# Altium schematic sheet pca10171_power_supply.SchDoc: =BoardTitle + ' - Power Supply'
size A3; Organization: Nordic Semiconductor; DocumentNumber: 8; SheetNumber: 8; SheetTotal: 10; CompanyName: Nordic Semiconductor; DocumentSize: A3
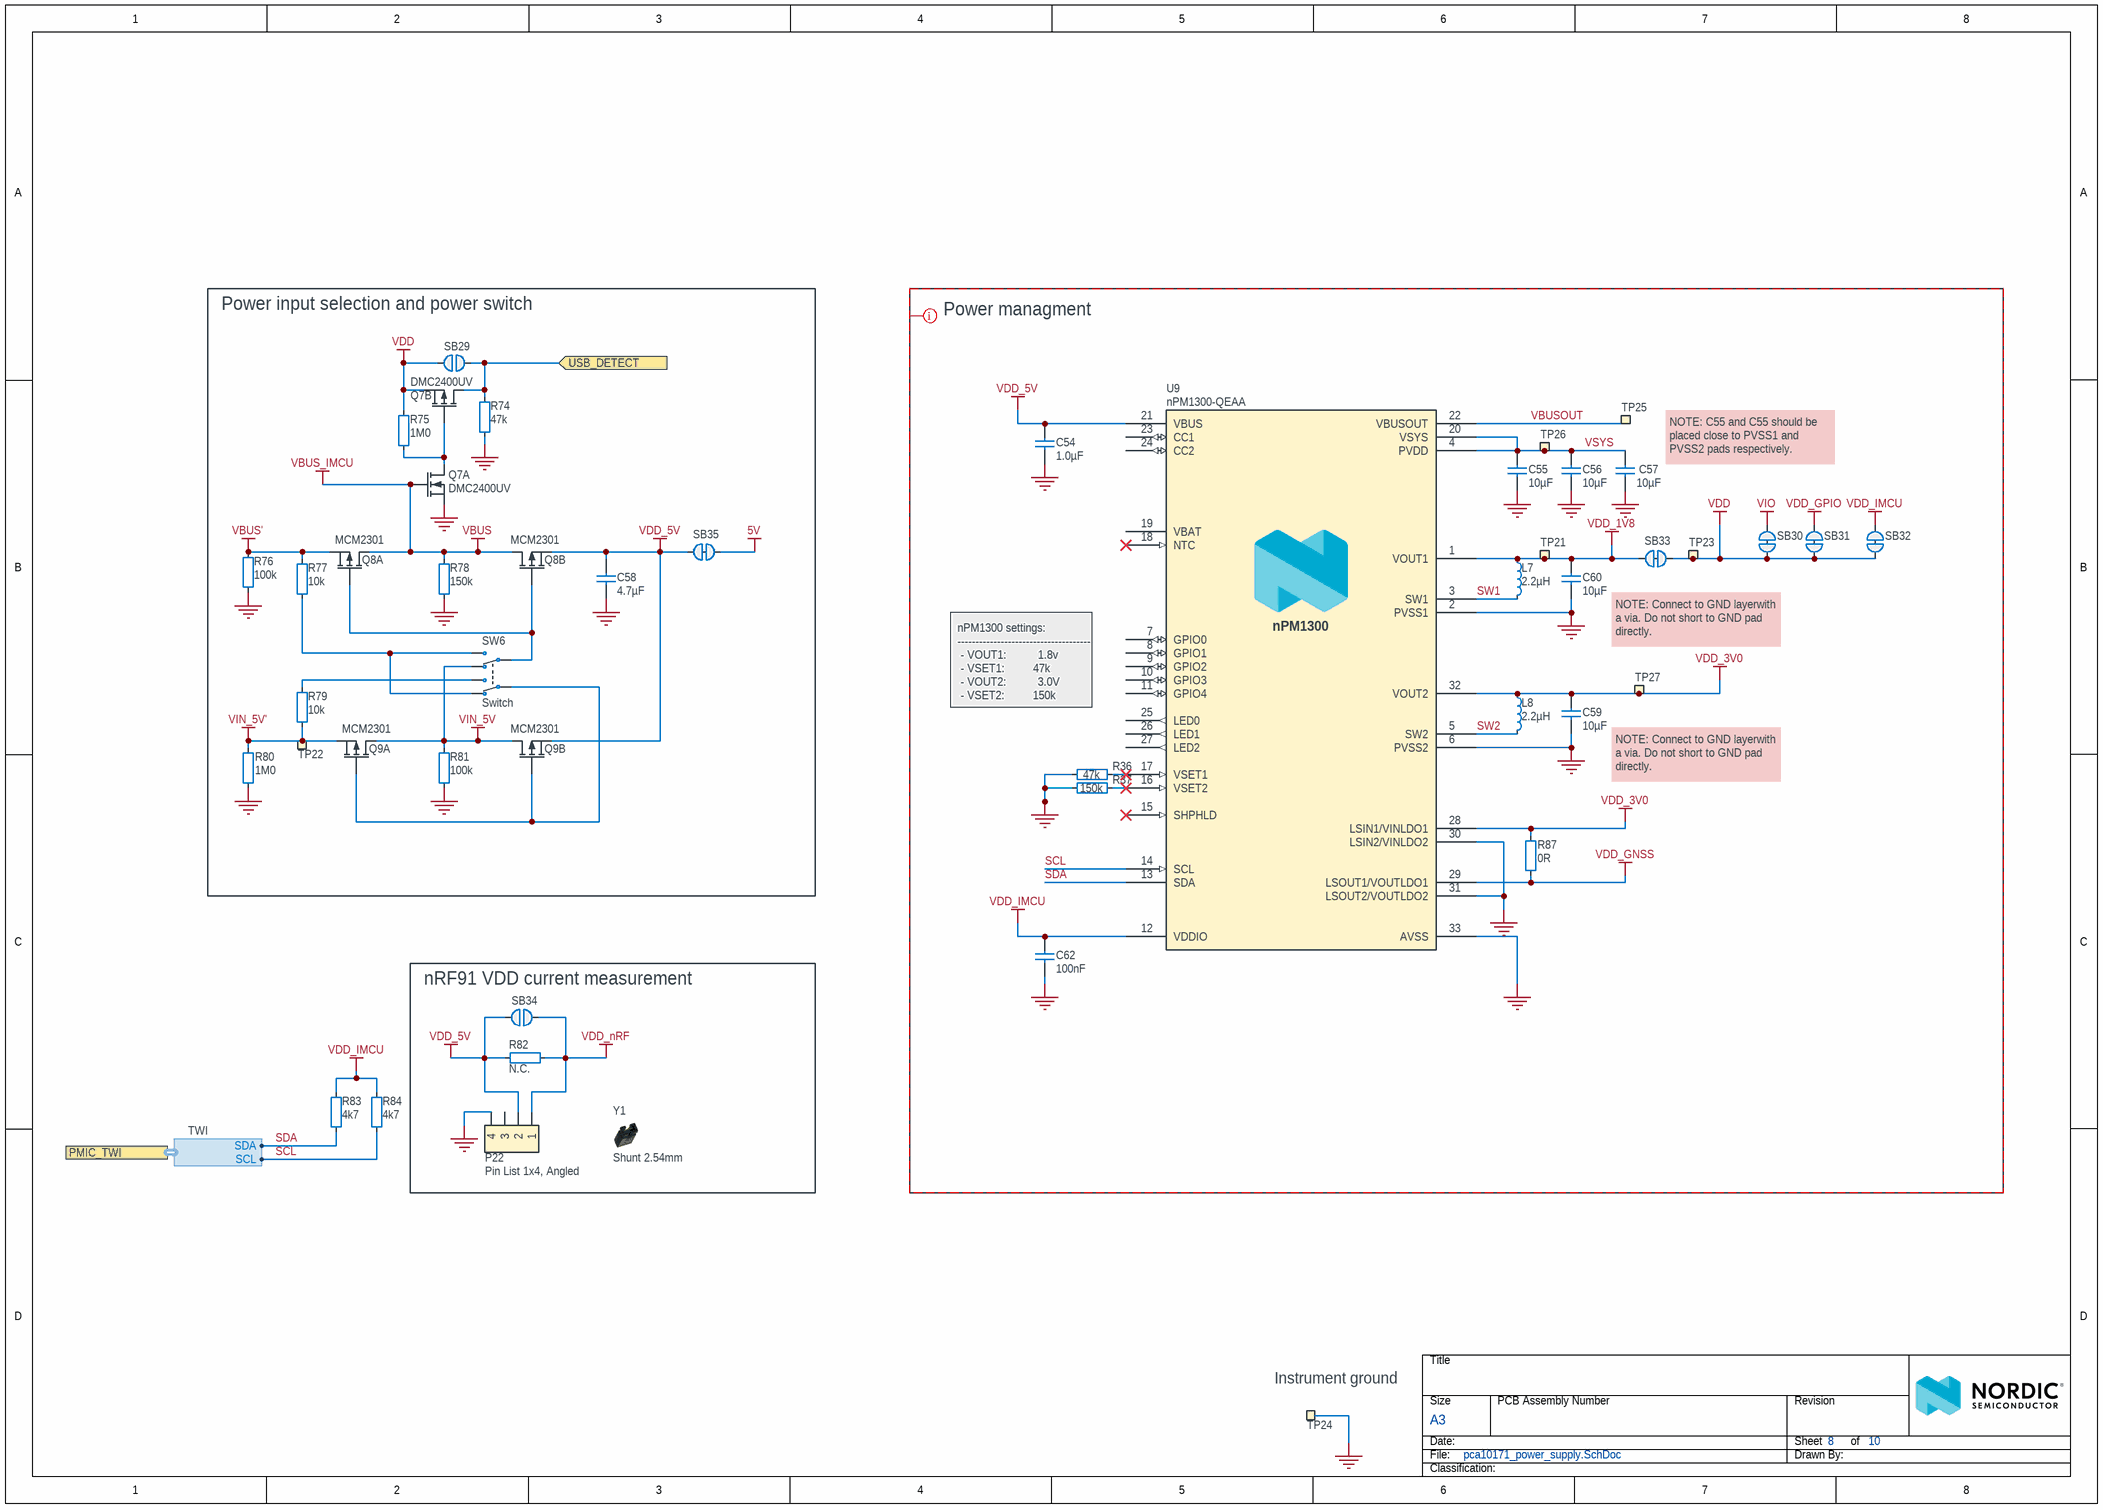
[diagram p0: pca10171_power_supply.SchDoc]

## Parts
C54  1.0µF  [CAPC1608X06L]
C55  10µF  [CAPC1608X06L]
C56  10µF  [CAPC1608X06L]
C57  10µF  [CAPC1608X06L]
C58  4.7µF  [CAPC1608X06L]
C59  10µF  [CAPC1608X06L]
C60  10µF  [CAPC1608X06L]
C62  100nF  [CAPC0603X03L_C]
L7  2.2µH  [INDC2016X10N]
L8  2.2µH  [INDC2016X10N]
P22  Pin List 1x4, Angled  [LIST_ANG_1x4-SMD-2.54MM]
Q7  DMC2400UV  [SOTFL50P162X60-6N]  (parts A,B of 2)
Q8  MCM2301  [DFN65P200X200X80_HS-6N]  (parts A,B of 2)
Q9  MCM2301  [DFN65P200X200X80_HS-6N]  (parts A,B of 2)
R36  47k  [RESC0603X03L_C]
R37  150k  [RESC0603X03L_C]
R74  47k  [RESC0603X03L_C]
R75  1M0  [RESC0603X03L_C]
R76  100k  [RESC0603X03L_C]
R77  10k  [RESC0603X03L_C]
R78  150k  [RESC0603X03L_C]
R79  10k  [RESC0603X03L_C]
R80  1M0  [RESC0603X03L_C]
R81  100k  [RESC0603X03L_C]
R82  N.C.  [RESC1005X04L_NC]
R83  4k7  [RESC0603X03L_C]
R84  4k7  [RESC0603X03L_C]
R87  0R  [RESC0603X03L_C]
SB29  Solderbridge  [Solderbridge]  (value not drawn)  (no BOM)
SB30  Solderbridge  [Solderbridge_Shorted_Power]  (value not drawn)  (net tie, no BOM)
SB31  Solderbridge  [Solderbridge_Shorted_Power]  (value not drawn)  (net tie, no BOM)
SB32  Solderbridge  [Solderbridge_Shorted]  (value not drawn)  (net tie, no BOM)
SB33  Solderbridge  [Solderbridge_Shorted_Power]  (value not drawn)  (net tie, no BOM)
SB34  Solderbridge  [Solderbridge]  (value not drawn)  (no BOM)
SB35  Solderbridge  [Solderbridge_Shorted_Power]  (value not drawn)  (net tie, no BOM)
SW6  Switch  [JS102011JAQN]
TP21  Ø1.5mm,SMD  [TP_SMD_D1.5mm]  (value not drawn)  (no BOM)
TP22  Ø1.5mm,SMD  [TP_SMD_D1.5mm]  (value not drawn)  (no BOM)
TP23  Ø1.5mm,SMD  [TP_SMD_D1.5mm]  (value not drawn)  (no BOM)
TP24  TP  [TESTPAD-TH]  (value not drawn)  (no BOM)
TP25  Ø1.5mm,SMD  [TP_SMD_D1.5mm]  (value not drawn)  (no BOM)
TP26  Ø1.5mm,SMD  [TP_SMD_D1.5mm]  (value not drawn)  (no BOM)
TP27  Ø1.5mm,SMD  [TP_SMD_D1.5mm]  (value not drawn)  (no BOM)
U9  nPM1300-QEAA  [Nordic_QFN50P500X500X90-33N]
Y1  Shunt 2.54mm  [Shunt_2.54mm_Horizontal]

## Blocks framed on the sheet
Power input selection and power switch: C58 Q7-Q9 R74-R81 SB29 SB35 SW6 TP22
Power managment: C54-C57 C59 C60 C62 L7 L8 R36 R37 R87 SB30-SB33 TP21 TP23 TP25-TP27 U9
nRF91 VDD current measurement: P22 R82 SB34 Y1

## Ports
PMIC_TWI (harness TWI), USB_DETECT (in)

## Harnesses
TWI: SCL, SDA

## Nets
5V: SB35.2
GND: C54.1 C55.1 C56.1 C57.1 C58.1 C59.1 C60.1 C62.2 P22.4 Q7.1(S1) R36.2 R37.2 R74.1 R76.2 R78.1 R80.2 R81.2 TP24.1 U9.2(PVSS1) U9.6(PVSS2) U9.30(LSIN2/VINLDO2) U9.31(LSOUT2/VOUTLDO2) U9.33(AVSS)
VBUS: Q7.2(G1) Q8.3(D2) Q8.6(D1) R78.2  [also labelled VBUS_IMCU]
VBUS': Q8.1(S1) R76.1 R77.1
VDD: Q7.4(S2) R75.1 SB29.1 SB30.2 SB31.1 SB32.1 SB33.2 TP23.1
VDD_1V8: C60.2 L7.1 SB33.1 TP21.1 U9.1(VOUT1)
VDD_3V0: C59.2 L8.1 R87.1 TP27.1 U9.28(LSIN1/VINLDO1) U9.32(VOUT2)
VDD_5V: C54.2 C58.2 P22.2 Q8.4(S2) Q9.4(S2) R82.2 SB34.2 SB35.1 U9.21(VBUS)
VDD_GNSS: R87.2 U9.29(LSOUT1/VOUTLDO1)
VDD_GPIO: SB31.2
VDD_IMCU: C62.1 R83.2 R84.2 SB32.2 U9.12(VDDIO)
VDD_nRF: P22.1 R82.1 SB34.1
VIN_5V: Q9.3(D2) Q9.6(D1) R81.1 SW6.6(N.C-2)
VIN_5V': Q9.1(S1) R79.2 R80.1 TP22.1
VIO: SB30.1
SCL: R84.1 U9.14(SCL) ; port PMIC_TWI.SCL
SDA: R83.1 U9.13(SDA) ; port PMIC_TWI.SDA
SW1: L7.2 U9.3(SW1)
SW2: L8.2 U9.5(SW2)
USB_DETECT: Q7.3(D2) R74.2 SB29.2 ; port USB_DETECT
VBUSOUT: TP25.1 U9.22(VBUSOUT)
VSYS: C55.2 C56.2 C57.2 TP26.1 U9.4(PVDD) U9.20(VSYS)
NetQ7_5: Q7.5(G2) Q7.6(D1) R75.2
NetQ8_2: Q8.2(G1) Q8.5(G2) SW6.5(COM-2)
NetQ9_2: Q9.2(G1) Q9.5(G2) SW6.2(COM-1)
NetR36_1: R36.1 U9.17(VSET1)
NetR37_1: R37.1 U9.16(VSET2)
NetR77_2: R77.2 SW6.3(N.C-1) SW6.4(N.O-2)
NetR79_1: R79.1 SW6.1(N.O-1)

Not connected (* = marked no-connect by the designer): P22 3; U9 7(GPIO0) 8(GPIO1) 9(GPIO2) 10(GPIO3) 11(GPIO4) 15(SHPHLD)* 18(NTC)* 19(VBAT) 23(CC1) 24(CC2) 25(LED0) 26(LED1) 27(LED2)

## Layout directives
CompClassName: nPM1300: GND, SCL, SDA, SW1, SW2, VBUSOUT, VDD, VDD_1V8, VDD_3V0, VDD_5V, VDD_GNSS, VDD_GPIO, VDD_IMCU, VIO, VSYS

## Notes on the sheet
- NOTE: C55 and C55 should be placed close to PVSS1 and PVSS2 pads respectively.
- NOTE: Connect to GND layerwith a via. Do not short to GND pad directly.
- nPM1300 settings:
  -------------------------------------
  - VOUT1:          1.8v
  - VSET1:	        47k
  - VOUT2:          3.0V
  - VSET2:	        150k
- (near TP24) Instrument ground

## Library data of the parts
C54 = C0603-1µ0-10V-X5R: Capacitor, Ceramic, 1.0µF 10V X5R 0603,±10%; Manufacturer: N.A.; Part number NEMS: 100200528; Component Status: Active; Pad Count: 2
C55-C57 C59 C60 = C0603-10µ-10V-X7T-GRM188D71A106MA73: Capacitor, X7T, ±20%, 10V; Manufacturer: Murata; Part number IPS: 00000004696; Part number NEMS: 100200414; Component Status: Active; Pad Count: 2; Note: 10VDC; Artikkelnr Noca: N.A.
C58 = C0603-4µ7-10V-X5R: Capacitor, Ceramic, X5R, ±10%, 10V; Manufacturer: N.A.; Part number Norautron: 262081761; Part number NEMS: 100200479; Pad Count: 2; Component Status: Active
C62 = C0201-100n: Capacitor, X5R, ±10%; Manufacturer: N.A.; Part number IPS: 00000001248, 00000002505; Part number Norautron: 262071862; Part number NEMS: 100200078; Pad Count: 2; Note: 16V; Component Status: Active
L7 L8 = L0806-2µ2-2500mA-73mOhm-CIGT201610EH2R2MNE: Inductor, Irms=2.5A, Isat=2.9A, ±20%, DCR=73mΩ; Manufacturer: Samsung Electro-Mechanics America; Part number Norautron: 26521789; Part number NEMS: 100300400; Component Status: Active; Pad Count: 2; Note: Unshielded Thin Film Inductor; Artikkelnr Noca: N.A.
P22 = Pin List Ang 1x4 SMD, 2.54mm: Pin List 1x4, 2.54mm (100mil), Right Angled, SMD; Manufacturer: WCON; Manufacturer Part Number: 1125B-1104S0Z135CR02; Part number IPS: 00000004780; Part number NEMS: 100500358; Note: N.A.; Pad Count: 4; Component Status: Active; System: Connector
Q7 = DMC2400UV: Dual N & P Ch MOFET, 1.03A/0.7A, 480mOhm, 450mW; Manufacturer: Diodes Incorporated; Part number IPS: 00000007803; Part number NEMS: 101300117; Note: Dual N & P Channel Digital FET; Artikkelnr Noca: N.A.; Pad Count: 6; Component Status: Active
Q8 Q9 = MCM2301: Dual P-Channel MOFET, 3.8A, 90mOhm max, 1.4W; Manufacturer: Micro Commercial Components; Part number NEMS: 101300199; Note: N.A.; Pad Count: 6; Component Status: Active
R36 = R0201-47k: Resistor, ±1%, 0.05W; Manufacturer: N.A.; Part number IPS: 00000001423; Part number NEMS: 100100076; Component Status: Active; Pad Count: 2; Note: Chip Res 1%
R37 = R0201-150k: Resistor, ±1%, 0.05W; Manufacturer: N.A.; Part number IPS: 00000001422; Part number NEMS: 100100082; Component Status: Active; Pad Count: 2; Note: Chip Res 1%
R74 = R0201-47k: Resistor, ±1%, 0.05W; Manufacturer: N.A.; Part number IPS: 00000001423; Part number NEMS: 100100076; Note: Chip Res 1%; Pad Count: 2; Component Status: Active
R75 R80 = R0201-1M0: Resistor, ±1%, 0.05W; Manufacturer: N.A.; Part number IPS: 00000001418; Part number Norautron: 26107108; Part number NEMS: 100100093; Note: Chip Res 1%; Pad Count: 2; Component Status: Active
R76 R81 = R0201-100k: Resistor, ±1%, 0.05W; Manufacturer: N.A.; Part number IPS: 00000001419; Part number Norautron: 26108487; Part number NEMS: 100100080; Note: Chip Res 1%; Pad Count: 2; Component Status: Active
R77 R79 = R0201-10k: Resistor, ±1%, 0.05W; Manufacturer: N.A.; Part number IPS: 00000001255; Part number Norautron: 26107101; Part number NEMS: 100100065; Note: Chip Res 1%; Pad Count: 2; Component Status: Active
R78 = R0201-150k: Resistor, ±1%, 0.05W; Manufacturer: N.A.; Part number IPS: 00000001422; Part number NEMS: 100100082; Note: Chip Res 1%; Pad Count: 2; Component Status: Active
R82 = R0402-N.C.: Not mounted; Manufacturer: N.A.; Part number NEMS: 100100281; Note: Chip Res; Assembly: Not mounted; Pad Count: 2; Component Status: Active
R83 R84 = R0201-4k7: Resistor, ±1%, 0.05W; Manufacturer: N.A.; Part number IPS: 00000001706; Part number NEMS: 100100061; Note: Chip Res 1%; Pad Count: 2; Component Status: Active
R87 = R0201-0R: Resistor, ±5%, 0.05W; Manufacturer: N.A.; Part number IPS: 00000003245; Part number NEMS: 100100001; Component Status: Active; Pad Count: 2; Note: Chip Res 5%
SB29 SB34 = Solderbridge: Manufacturer: N.A.; Part number NEMS: 100500458; Pad Count: 2; Component Status: Active; System: Connector
SB30 SB31 SB33 SB35 = Solderbridge Shorted Power: Shorted Solderbridge Power; Manufacturer: N.A.; Part number NEMS: 100500460; Pad Count: 2; Component Status: Active; System: Connector
SB32 = Solderbridge Shorted: Shorted Solderbridge; Manufacturer: N.A.; Part number NEMS: 100500459; Pad Count: 2; Component Status: Active; System: Connector
SW6 = Switch-Slide-RA-J-Lead-DPDT-8.5x3.5mm_C&K: SMD slide Switch (ON-ON); Manufacturer: C&K; Manufacturer Part Number: JS202011JAQN; Part number IPS: 00000007811; Part number NEMS: 101500037; Note: N.A.; Pad Count: 6; Component Status: Active
TP21-TP23 TP25-TP27 = TP_SMD_Ø1.5MM: 1.5mm circular SMD testpad; Manufacturer: Nordic Semiconductor; Manufacturer Part Number: N.A.; Part number NEMS: 100500477; Pad Count: 1; Component Status: Active
TP24 = Testpoint TH: Testpoint, through hole; Manufacturer: N.A.; Part number NEMS: 100500464; Pad Count: 1; Component Status: Active
U9 = nPM1300-QEAA: Li-Ion/Li-Polymer USB-C battery charger with high efficiency buck regulators, LDOs or load switches, LED drivers, TWI and VBUSOUT; Manufacturer: Nordic Semiconductor; Part number NEMS: 102000291; Component Status: Active; Pad Count: 33; Note: N.A.
Y1 = SHUNT JUMPER 2.54mm BLACK GOLD Horizontal (obsolete): Shunt Jumper 2.54mm Black; Manufacturer: 3M; Manufacturer Part Number: 969102-0000-DA; Part number IPS: 00000001916; Part number Norautron: N.A.; Part number NEMS: 100500644; Assembly: Placed on "VDD" pins of P22; Note: SHUNT JUMPER .1" BLACK GOLD, h=6.00mm, w=5.00mm; Artikkelnr Noca: 56099001; Pad Count: 2; System: Connector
